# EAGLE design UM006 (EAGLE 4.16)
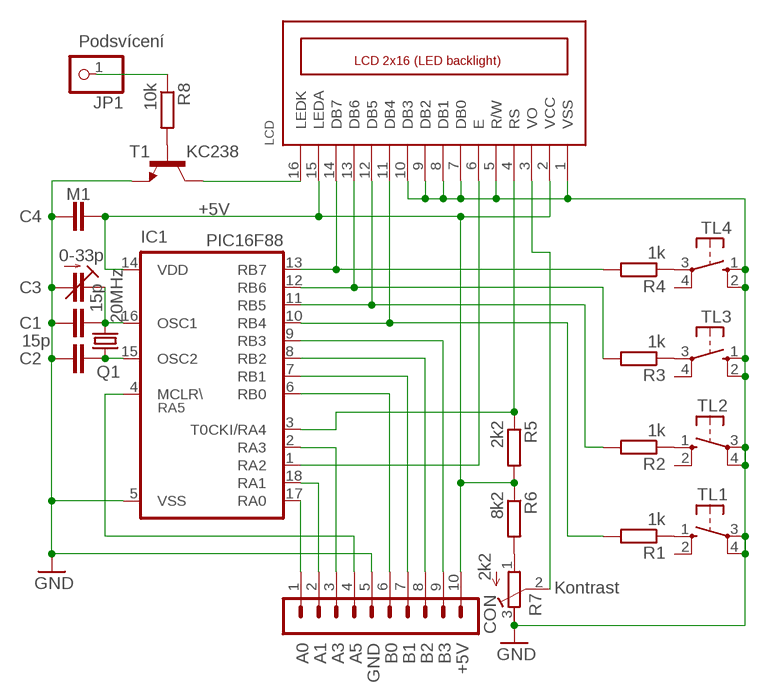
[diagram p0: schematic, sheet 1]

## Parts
C1  15p  C-EU025-024X044  [C025-024X044]
C2  15p  C-EU025-024X044  [C025-024X044]
C3  0-33p  C-TRIMM3008  [CTRIM3008]
C4  M1  C-EU025-024X044  [C025-024X044]
CON  MA10-1  [MA10-1]
IC1  PIC16F88  PIC16F84AP  [DIL18]
JP1  Podsvícení  PINHD-1X1  [1X01]
LCD  EL1602A  LCD_2X16_SIL  [HY-1602F]
Q1  20MHz  CRYSTALHC49U-H  [HC49U-H]
R1  1k  R-EU_0207/10  [0207/10]
R2  1k  R-EU_0207/10  [0207/10]
R3  1k  R-EU_0207/10  [0207/10]
R4  1k  R-EU_0207/10  [0207/10]
R5  2k2  R-EU_0204/5  [0204/5]
R6  8k2  R-EU_0204/2V  [0204V]
R7  2k2  R-TRIMM3339P  [RTRIM3339P]
R8  10k  R-EU_0207/10  [0207/10]
T1  KC238  BC548  [TO92-EBC]
TL1  10-XX  [B3F-10XX]
TL2  10-XX  [B3F-10XX]
TL3  10-XX  [B3F-10XX]
TL4  10-XX  [B3F-10XX]

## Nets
+5V: C4.1 CON.10 IC1.14(VDD) LCD.2(VCC) LCD.15(LEDA) R5.2 R6.1
A0: CON.1 IC1.17(RA0)
A1: CON.2 IC1.18(RA1)
A2_E: IC1.1(RA2) LCD.6(E)
A3: CON.3 IC1.2(RA3)
A4_RS: IC1.3(T0CKI/RA4) LCD.4(RS) R5.1
A5: CON.4 IC1.4(MCLR\)
B0: CON.6 IC1.6(RB0)
B1: CON.7 IC1.7(RB1)
B2: CON.8 IC1.8(RB2)
B3: CON.9 IC1.9(RB3)
B4_DB4: IC1.10(RB4) LCD.11(DB4) R1.2
B5_DB5: IC1.11(RB5) LCD.12(DB5) R2.2
B6_DB6: IC1.12(RB6) LCD.13(DB6) R3.2
B7_DB7: IC1.13(RB7) LCD.14(DB7) R4.2
GND: C1.1 C2.1 C3.-(A) C4.2 CON.5 IC1.5(VSS) LCD.1(VSS) LCD.5(R/W) LCD.7(DB0) LCD.8(DB1) LCD.9(DB2) LCD.10(DB3) R7.3(A) T1.E TL1.3(P) TL1.4(P1) TL2.3(P) TL2.4(P1) TL3.1(S) TL3.2(S1) TL4.1(S) TL4.2(S1)
LEDK: LCD.16(LEDK) T1.C
N$1: R6.2 R7.1(E)
N$11: R8.2 T1.B
N$26: JP1.1 R8.1
N$152: R4.1 TL4.3(P)
N$153: R3.1 TL3.3(P)
OSC1: C1.2 C3.+(E) IC1.16(OSC1) Q1.2
OSC2: C2.2 IC1.15(OSC2) Q1.1
TL1: R1.1 TL1.1(S)
TL2: R2.1 TL2.1(S)
VO: LCD.3(VO) R7.2(S)
Unconnected: TL1.2(S1) TL2.2(S1) TL3.4(P1) TL4.4(P1)

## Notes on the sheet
- +5V
- RA5
- Kontrast
- A0 | A1 | A3 | A5 | GND | B0 | B1 | B2 | B3 | +5V

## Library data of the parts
C1 C2 C4 = rcl:C-EU: CAPACITOR, European symbol
C3 = rcl:C-TRIMM: Trimm capacitor
CON = con-lstb:MA10-1: PIN HEADER
IC1 = microchip:PIC16F8*: MICROCONTROLLER 8-Bit PIC16F8X Family - CMOS Flash/EEPROM Pin Compatible : PIC16F83, PIC16CR83, PIC16F84A, PIC16CR84 see also PIC16C*
JP1 = pinhead:PINHD-1X1: PIN HEADER
LCD = lcd_2x16_led_backlight:LCD_2X16_SIL
Q1 = crystal:CRYSTAL: CRYSTAL
R1-R6 R8 = rcl:R-EU_: RESISTOR, European symbol
R7 = rcl:R-TRIMM: Trimm resistor
T1 = transistor-npn:BC548*: NPN Transistor
TL1-TL4 = switch-omron:10-XX: OMRON SWITCH

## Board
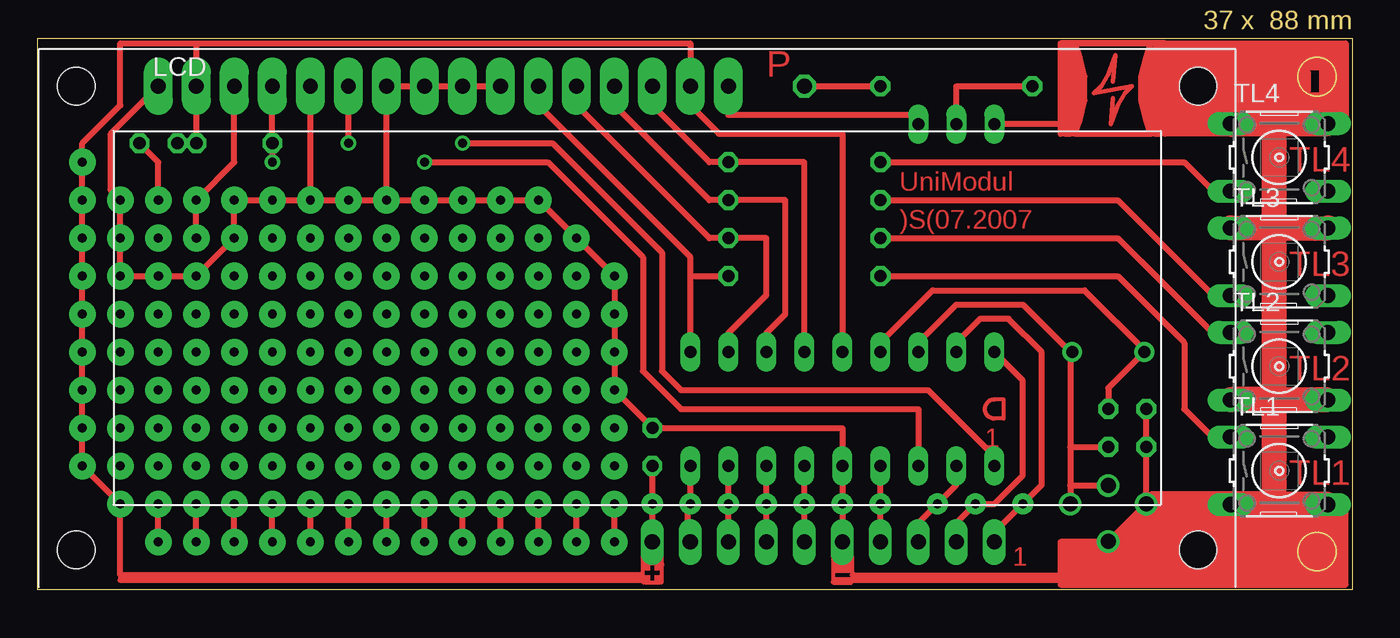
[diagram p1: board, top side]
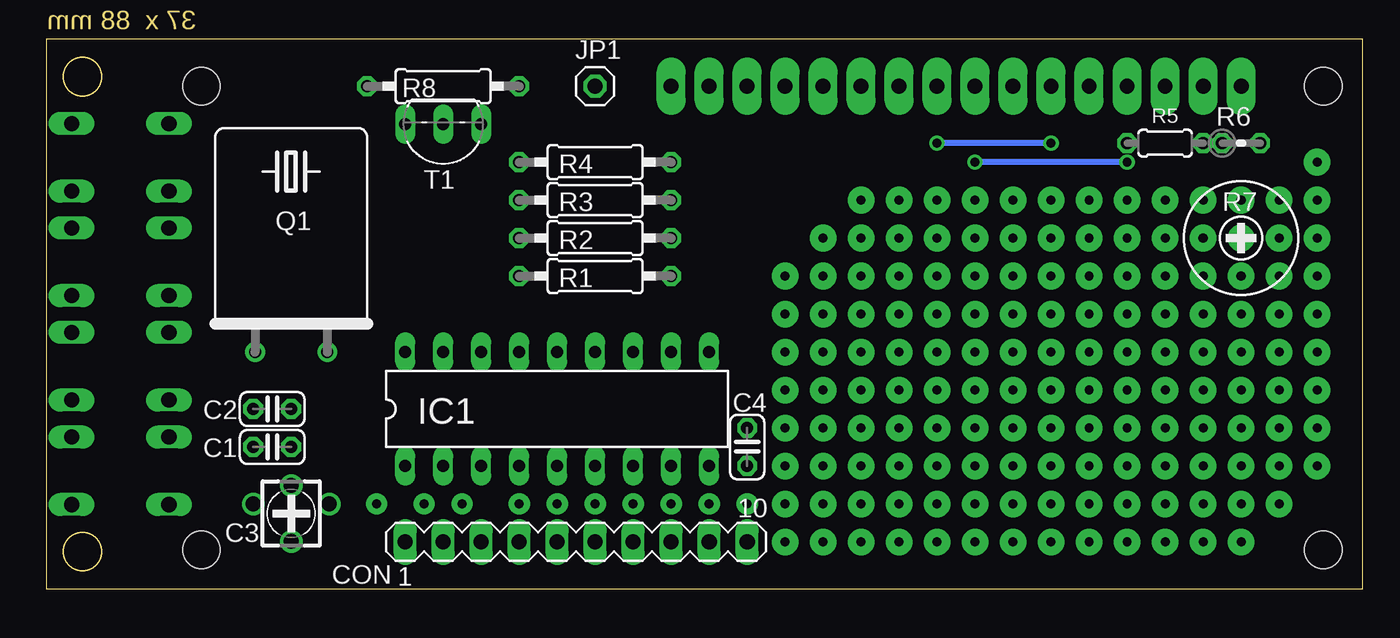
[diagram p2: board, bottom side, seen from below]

Size 87.94 x 36.82 mm. Coordinates in mm from the lower left corner, seen from the top.
Outline: 0,0 87.94,0 87.94,36.82 0,36.82 0,0
Outline: circle at 85.56,34.29 radius 1.27
Outline: circle at 85.56,2.54 radius 1.27
Copper layers (1*16): Top 0.035mm / dielectric 1.5mm / Bottom 0.035mm
Design rules "default": minimum track width 10mil, minimum drill 24mil, track to track 8mil, track to pad 8mil, pad to pad 8mil, via to via 8mil, smd to smd 8mil, copper to edge 40mil, drill to drill 8mil, minimum pad ring 10mil, minimum via ring 8mil, stop-mask expansion 4mil, vias tented up to drill 0mil, thermal gap 10mil

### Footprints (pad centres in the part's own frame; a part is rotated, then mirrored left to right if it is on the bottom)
C025-024X044 = drill 0.813 octagon: 1 -1.27,0; 2 1.27,0
CTRIM3008 = drill 1 round: + -1.875,0; - 1.875,0
MA10-1 = drill 1.016 long: 1 -11.43,0; 2 -8.89,0; 3 -6.35,0; 4 -3.81,0; 5 -1.27,0; 6 1.27,0; 7 3.81,0; 8 6.35,0; 9 8.89,0; 10 11.43,0
DIL18 = drill 0.813 long: 1 -10.16,-3.81; 2 -7.62,-3.81; 3 -5.08,-3.81; 4 -2.54,-3.81; 5 0,-3.81; 6 2.54,-3.81; 7 5.08,-3.81; 8 7.62,-3.81; 9 10.16,-3.81; 10 10.16,3.81; 11 7.62,3.81; 12 5.08,3.81; 13 2.54,3.81; 14 0,3.81; 15 -2.54,3.81; 16 -5.08,3.81; 17 -7.62,3.81; 18 -10.16,3.81
1X01 = drill 1.016 octagon: 1 0,0
HY-1602F = drill 1 pad 1.93 long: 1 2.54,0; 2 5.08,0; 3 7.62,0; 4 10.16,0; 5 12.7,0; 6 15.24,0; 7 17.78,0; 8 20.32,0; 9 22.86,0; 10 25.4,0; 11 27.94,0; 12 30.48,0; 13 33.02,0; 14 35.56,0; 15 38.1,0; 16 40.64,0 | hole 2.5: -2.96,0; 72.04,0; -2.96,-31; 72.04,-31
HC49U-H = drill 0.813 round: 1 -2.413,-5.08; 2 2.413,-5.08
0207/10 = drill 0.813 octagon: 1 -5.08,0; 2 5.08,0
0204/5 = drill 0.813 octagon: 1 -2.54,0; 2 2.54,0
0204V = drill 0.813 octagon: 1 -1.27,0; 2 1.27,0
RTRIM3339P = drill 0.61 round: 1 -2.54,0; 2 0,-2.54; 3 2.54,0
TO92-EBC = drill 0.813 long: B 0,-1.27; C -2.54,-1.27; E 2.54,-1.27
B3F-10XX = drill 1.016 long: 1 -3.251,2.261; 2 3.251,2.261; 3 -3.251,-2.261; 4 3.251,-2.261

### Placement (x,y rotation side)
C1  72.86,9.52 0 bottom
C2  72.86,12.06 0 bottom
C3  71.59,5.08 270 bottom
C4  41.11,9.52 90 bottom
CON  52.54,3.17 0 bottom
IC1  53.81,12.06 0 bottom
JP1  51.27,33.65 0 bottom
LCD  5.55,33.65 0 top
Q1  71.59,20.95 0 bottom
R1  51.27,20.95 0 bottom
R2  51.27,23.49 0 bottom
R3  51.27,26.03 0 bottom
R4  51.27,28.57 0 bottom
R5  13.17,29.84 0 bottom
R6  8.09,29.84 0 bottom
R7  8.09,23.49 270 bottom
R8  61.43,33.65 180 bottom
T1  61.43,29.84 180 bottom
TL1  83.02,7.93 0 top
TL2  83.02,14.92 0 top
TL3  83.02,21.9 0 top
TL4  83.02,28.89 0 top

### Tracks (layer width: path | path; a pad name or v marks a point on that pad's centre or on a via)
+5V  (via drill 0.6 pad 1.42)
  Top 0.254: 40.48,0.95 40.32,0.95 | 40.48,0.95 40.48,2.22 41.11,2.85 41.75,2.22 41.75,1.58 | 41.75,1.58 41.75,0.47 40.48,0.47 40.48,0.63 40.48,0.95 | 41.75,1.58 41.75,1.74 40.48,1.74 40.48,0.95
  Top 0.406: 10.63,36.51 LCD.2 R5.2 R6.1 | 10.63,36.51 43.65,36.51 LCD.15 43.65,32.38 45.55,30.47 53.81,30.47 IC1.14 | 10.63,36.51 5.55,36.51 5.55,32.38 3.01,29.84 3.01,8.25 5.55,5.71 5.55,0.95 40.32,0.95 | 5.55,0.63 40.48,0.63 | C4.1 v41.11,5.71 CON.10 | CON.10 | CON.10 41.11,2.85
A0
  Top 0.406: IC1.17 61.43,16.5 63.02,18.09 64.92,18.09 67.14,15.87 67.14,6.98 63.97,3.8 CON.1
A1
  Top 0.406: IC1.18 65.88,13.96 65.88,7.62 63.97,5.71 62.7,5.71 61.43,4.44 CON.2
A2_E  (via drill 0.6)
  Top 0.406: v20.79,29.84 LCD.6 | IC1.1 63.97,8.88 59.53,13.33 43.02,13.33 41.75,14.6 41.75,22.54 34.44,29.84 v28.41,29.84
  Bottom 0.406: v20.79,29.84 v28.41,29.84
A3
  Top 0.406: IC1.2 61.43,6.98 58.89,4.44 CON.3
A4_RS  (via drill 0.6)
  Top 0.406: IC1.3 58.89,12.06 43.02,12.06 40.48,14.6 40.48,22.22 34.12,28.57 v25.87,28.57 | LCD.4 R5.1 v15.71,28.57
  Bottom 0.406: v15.71,28.57 v25.87,28.57
A5  (via drill 0.6 pad 1.42)
  Top 0.406: IC1.4 v56.35,5.71 CON.4
B0  (via drill 0.6 pad 1.42)
  Top 0.406: IC1.6 v51.27,5.71 CON.6
B1  (via drill 0.6 pad 1.42)
  Top 0.406: IC1.7 v48.73,5.71 CON.7
B2  (via drill 0.6 pad 1.42)
  Top 0.406: IC1.8 v46.19,5.71 CON.8
B3  (via drill 0.6 pad 1.42)
  Top 0.406: IC1.9 v43.65,5.71 43.49,5.71 43.49,3.17 CON.9
B4_DB4
  Top 0.406: IC1.10 43.65,20.95 | LCD.11 33.49,32.38 43.65,22.22 43.65,20.95 | 43.65,20.95 R1.2
B5_DB5
  Top 0.406: LCD.12 36.03,32.38 44.92,23.49 R2.2 48.73,23.49 48.73,19.68 46.19,17.14 IC1.11
B6_DB6
  Top 0.406: LCD.13 38.57,32.38 44.92,26.03 R3.2 50,26.03 50,18.41 48.73,17.14 IC1.12
B7_DB7
  Top 0.406: LCD.14 41.11,32.38 44.92,28.57 R4.2 51.27,28.57 IC1.13
GND  (via drill 0.6 pad 1.42, 0.6 pad 1.78, 1)
  Top 0.254: 54.45,0.95 54.6,0.95 | 54.45,0.95 54.45,2.22 53.81,2.85 53.73,2.77 53.18,2.22 53.18,0.47 | 54.45,0.47 54.45,0.63 54.45,0.95
  Top 0.406: 83.02,5.71 83.02,12.7 83.02,24.12 83.02,31.11 TL4.1 79.77,30.47 | 54.6,0.95 71.59,0.95 71.59,3.17 | 83.02,5.71 83.34,5.71 83.34,30.79 | 80.16,5.71 80.48,5.71 | 80.48,5.71 80.8,5.71 | 80.8,5.71 81.75,5.71 | 82.07,5.71 82.39,5.71 | 82.7,5.71 83.02,5.71 | 79.84,5.71 79.81,5.71 | 79.84,5.71 79.81,5.67 TL1.3 79.73,5.71 78.89,5.71 | TL1.4 86.23,5.67 86.2,5.71 86.23,5.71 | TL2.4 86.23,12.66 86.2,12.7 86.23,12.7 | 79.81,12.7 TL2.3 | v74.13,5.71 74.45,5.71 | 74.45,5.71 74.77,5.71 | 75.4,5.71 75.08,5.71 | 76.67,5.71 75.72,5.71 | 76.99,5.71 77.31,5.71 | 77.62,5.71 77.94,5.71 | 78.26,5.71 78.58,5.71 | 72.54,4.12 71.62,3.2 | 72.54,4.12 73.5,5.08 | 73.81,5.39 v74.13,5.71 | LCD.10 LCD.9 LCD.8 LCD.7 23.33,26.03 | LCD.1 4.92,30.47 4.92,26.66 v5.55,26.03 v5.55,20.95 R7.3 10.63,20.95 13.17,23.49 v13.17,26.03 v15.71,26.03 v18.25,26.03 | 23.33,26.03 33.49,26.03 38.57,20.95 38.57,13.33 C4.2 53.81,10.79 IC1.5 v53.81,5.71 CON.5 | v18.25,26.03 23.33,26.03 | v18.25,26.03 LCD.5 | 79.77,30.47 79.84,31.11 | 75.4,30.47 69.37,30.47 | 69.37,30.47 68.42,30.47 68.42,31.11 | 69.37,30.47 74.45,30.47 74.13,31.43 73.81,32.7 73.81,34.29 74.13,35.56 74.45,36.51 69.37,36.51 69.69,35.56 70,34.29 70,32.7 69.69,31.43 69.37,30.47 | 68.42,31.11 68.42,36.51 75.4,36.51 | 75.4,30.79 75.4,31.11 | 75.4,31.11 75.4,36.51 | 75.4,36.51 87.47,36.51 87.47,31.43 75.72,31.43 75.72,36.19 87.15,36.19 87.15,31.75 76.03,31.75 76.03,35.87 86.83,35.87 86.83,32.06 76.35,32.06 76.35,35.56 86.51,35.56 86.51,32.38 76.67,32.38 76.67,35.24 86.2,35.24 86.2,32.7 76.99,32.7 76.99,34.92 85.88,34.92 85.88,33.02 77.31,33.02 77.31,34.6 84.92,34.6 84.92,34.29
  Top 0.406: 84.92,33.65 84.92,33.33 77.62,33.33 77.62,34.29 84.92,34.29 | 84.92,34.29 84.92,33.97 | 84.92,33.97 84.92,33.65 | 84.92,33.65 77.94,33.65 77.94,33.97 84.92,33.97 | 82.7,5.71 82.7,31.11 | 82.39,5.71 82.7,5.71 | 82.39,5.71 82.39,30.79 82.07,30.79 | 82.07,6.35 82.07,30.47 | 82.07,6.03 82.07,6.35 | 82.07,5.71 82.07,6.03 | 87.47,5.71 87.47,0.31 68.42,0.31 68.42,0.63 | 68.42,0.63 68.42,3.17 71.59,3.17 | 71.59,3.17 71.59,0.63 | 71.59,0.63 68.73,0.63 68.73,2.85 71.27,2.85 71.27,1.26 | 81.12,0.63 81.43,0.63 | 81.75,0.63 87.15,0.63 | 87.15,0.95 87.15,5.71 86.83,5.71 86.83,0.95 86.51,0.95 86.51,5.39 86.2,5.39 86.2,0.95 85.88,0.95 85.88,5.39 85.56,5.39 85.56,0.95 85.24,0.95 85.24,5.39 84.92,5.39 84.92,0.95 84.61,0.95 | 84.61,5.71 84.29,5.71 84.29,0.95 83.97,0.95 83.97,5.39 83.66,5.39 83.66,0.95 83.34,0.95 83.34,5.39 83.02,5.39 83.02,0.95 | 82.7,0.95 82.7,5.39 82.39,5.39 82.39,0.95 82.07,0.95 82.07,5.71 | 81.75,5.71 82.07,5.71 | 81.75,0.63 81.75,5.71 | 81.43,0.63 81.75,0.63 | 81.43,0.63 81.43,5.39 81.12,5.39 81.12,0.63 | 71.59,0.63 71.91,0.63 | 72.23,0.63 76.35,0.63 | 76.67,0.63 79.53,0.63 | 79.84,0.63 80.16,0.63 | 80.48,0.63 81.12,0.63 | 80.8,5.71 80.8,0.95 | 80.48,0.63 80.48,5.71 | 80.16,0.63 80.48,0.63 | 80.16,0.63 80.16,5.71 | 79.84,5.71 80.16,5.71 | 79.84,0.63 79.84,5.71 | 79.53,0.63 79.84,0.63 | 79.53,0.63 79.53,5.39 79.21,5.39 79.21,0.95 78.89,0.95 78.89,5.71 | 78.89,5.71 78.58,5.71 | 78.58,5.71 78.58,0.95 78.26,0.95 78.26,5.71 | 77.94,5.71 78.26,5.71 | 77.94,5.71 77.94,0.95 77.62,0.95 77.62,5.71 | 77.31,5.71 77.62,5.71 | 77.31,5.71 77.31,0.95 76.99,0.95 76.99,5.71 | 76.67,5.71 76.99,5.71 | 76.67,0.63 76.67,5.71
  Top 0.406: 76.35,0.63 76.67,0.63 | 76.35,0.63 76.35,5.39 76.03,5.39 76.03,0.95 75.72,0.95 75.72,5.71 | 75.72,5.71 75.4,5.71 | 75.4,5.71 75.4,0.95 75.08,0.95 75.08,5.71 | 75.08,5.71 74.77,5.71 | 74.77,5.71 74.77,0.95 74.45,0.95 74.45,5.71 | 74.45,5.71 74.13,5.39 74.13,0.95 73.81,0.95 73.81,5.39 | 73.5,5.08 73.81,5.39 | 73.5,5.08 73.5,0.95 73.18,0.95 73.18,4.44 72.86,4.12 72.86,0.95 72.54,0.95 72.54,4.12 | 72.54,4.12 72.23,3.49 72.23,0.63 | 71.91,0.63 72.23,0.63 | 71.91,0.63 71.91,3.17 | 75.4,31.11 79.53,31.11 79.53,30.79 75.4,30.79 | 75.4,30.47 75.4,30.79 | 79.77,30.47 75.4,30.47 | 82.07,30.47 79.84,30.47 | 82.07,30.79 82.07,30.47 | 82.07,30.79 80.16,30.79 | 82.07,6.03 74.45,6.03 74.45,6.35 82.07,6.35 | 54.45,0.63 68.42,0.63 | 68.42,31.11 T1.E | C2.1 C1.1 v74.13,5.71 | 71.59,3.17 C3.- | CON.5 | 53.81,2.77 53.81,2.69 | 53.81,2.77 53.73,2.77 | CON.5 53.81,2.77
  Top 1.676: 83.34,5.71 84.29,5.71 | 86.2,5.71 84.61,5.71 84.61,0.95 | 86.2,12.7 83.02,12.7 79.81,12.7 | 83.02,31.11 TL4.2 | TL3.2 83.02,24.12 TL3.1
LEDK
  Top 0.406: LCD.16 46.19,31.75 58.89,31.75 T1.C
N$1
  Top 0.406: R7.1 8.09,28.57 R6.2
N$2  (via drill 0.6 pad 1.78)
  other vias: 8.09,23.49
N$3  (via drill 0.6 pad 1.78)
  other vias: 8.09,20.95
N$4  (via drill 0.6 pad 1.78)
  other vias: 13.17,23.49
N$5  (via drill 0.6 pad 1.78)
  other vias: 10.63,26.03
N$6  (via drill 0.6 pad 1.78)
  other vias: 10.63,20.95
N$7  (via drill 0.6 pad 1.78)
  other vias: 5.55,23.49
N$8  (via drill 0.6 pad 1.78)
  other vias: 8.09,26.03
N$9  (via drill 0.6 pad 1.78)
  other vias: 23.33,26.03
N$11
  Top 0.406: T1.B 61.43,33.65 R8.2
N$12  (via drill 0.6 pad 1.78)
  other vias: 20.79,26.03
N$13  (via drill 0.6 pad 1.78)
  other vias: 10.63,23.49
N$14  (via drill 0.6 pad 1.78)
  other vias: 38.57,13.33
N$15  (via drill 0.6 pad 1.78)
  other vias: 38.57,15.87
N$16  (via drill 0.6 pad 1.78)
  other vias: 38.57,18.41
N$17  (via drill 0.6 pad 1.78)
  other vias: 38.57,20.95
N$18  (via drill 0.6 pad 1.78)
  other vias: 36.03,23.49
N$19  (via drill 0.6 pad 1.78)
  other vias: 33.49,26.03
N$20  (via drill 0.6 pad 1.78)
  other vias: 30.95,26.03
N$21  (via drill 0.6 pad 1.78)
  other vias: 28.41,26.03
N$22  (via drill 0.6 pad 1.78)
  other vias: 25.87,26.03
N$23  (via drill 0.6 pad 1.78)
  other vias: 5.55,5.71
N$24  (via drill 0.6 pad 1.78)
  other vias: 38.57,10.79
N$25  (via drill 0.6 pad 1.78)
  other vias: 3.01,8.25
N$26
  Top 0.406: 51.11,33.65 JP1.1 R8.1
N$27  (via drill 0.6 pad 1.78)
  other vias: 38.57,8.25
N$28  (via drill 0.6 pad 1.78)
  Top 0.406: v38.57,3.17 v38.57,5.71
N$30  (via drill 0.6 pad 1.78)
  other vias: 36.03,20.95
N$31  (via drill 0.6 pad 1.78)
  other vias: 36.03,18.41
N$32  (via drill 0.6 pad 1.78)
  other vias: 36.03,15.87
N$33  (via drill 0.6 pad 1.78)
  other vias: 36.03,13.33
N$34  (via drill 0.6 pad 1.78)
  other vias: 36.03,10.79
N$35  (via drill 0.6 pad 1.78)
  other vias: 36.03,8.25
N$36  (via drill 0.6 pad 1.78)
  Top 0.406: v36.03,3.17 v36.03,5.71
N$38  (via drill 0.6 pad 1.78)
  other vias: 33.49,23.49
N$39  (via drill 0.6 pad 1.78)
  other vias: 33.49,20.95
N$40  (via drill 0.6 pad 1.78)
  other vias: 33.49,18.41
N$41  (via drill 0.6 pad 1.78)
  other vias: 33.49,15.87
N$42  (via drill 0.6 pad 1.78)
  other vias: 33.49,13.33
N$43  (via drill 0.6 pad 1.78)
  other vias: 33.49,10.79
N$44  (via drill 0.6 pad 1.78)
  other vias: 33.49,8.25
N$45  (via drill 0.6 pad 1.78)
  Top 0.406: v33.49,3.17 v33.49,5.71
N$48  (via drill 0.6 pad 1.78)
  Top 0.406: v30.95,3.17 v30.95,5.71
N$49  (via drill 0.6 pad 1.78)
  other vias: 30.95,8.25
N$50  (via drill 0.6 pad 1.78)
  other vias: 30.95,10.79
N$51  (via drill 0.6 pad 1.78)
  other vias: 30.95,13.33
N$52  (via drill 0.6 pad 1.78)
  other vias: 30.95,15.87
N$53  (via drill 0.6 pad 1.78)
  other vias: 30.95,18.41
N$54  (via drill 0.6 pad 1.78)
  other vias: 30.95,20.95
N$55  (via drill 0.6 pad 1.78)
  other vias: 30.95,23.49
N$56  (via drill 0.6 pad 1.78)
  other vias: 28.41,23.49
N$57  (via drill 0.6 pad 1.78)
  other vias: 28.41,20.95
N$58  (via drill 0.6 pad 1.78)
  other vias: 28.41,18.41
N$59  (via drill 0.6 pad 1.78)
  other vias: 28.41,15.87
N$60  (via drill 0.6 pad 1.78)
  other vias: 28.41,13.33
N$61  (via drill 0.6 pad 1.78)
  other vias: 28.41,10.79
N$62  (via drill 0.6 pad 1.78)
  other vias: 28.41,8.25
N$63  (via drill 0.6 pad 1.78)
  Top 0.406: v28.41,3.17 v28.41,5.71
N$66  (via drill 0.6 pad 1.78)
  Top 0.406: v25.87,3.17 v25.87,5.71
N$67  (via drill 0.6 pad 1.78)
  other vias: 25.87,8.25
N$68  (via drill 0.6 pad 1.78)
  other vias: 25.87,10.79
N$69  (via drill 0.6 pad 1.78)
  other vias: 25.87,13.33
N$70  (via drill 0.6 pad 1.78)
  other vias: 25.87,15.87
N$71  (via drill 0.6 pad 1.78)
  other vias: 25.87,18.41
N$72  (via drill 0.6 pad 1.78)
  other vias: 25.87,20.95
N$73  (via drill 0.6 pad 1.78)
  other vias: 25.87,23.49
N$74  (via drill 0.6 pad 1.78)
  other vias: 23.33,23.49
N$75  (via drill 0.6 pad 1.78)
  other vias: 23.33,20.95
N$76  (via drill 0.6 pad 1.78)
  other vias: 23.33,18.41
N$77  (via drill 0.6 pad 1.78)
  other vias: 23.33,15.87
N$78  (via drill 0.6 pad 1.78)
  other vias: 23.33,13.33
N$79  (via drill 0.6 pad 1.78)
  other vias: 23.33,10.79
N$80  (via drill 0.6 pad 1.78)
  other vias: 23.33,8.25
N$81  (via drill 0.6 pad 1.78)
  Top 0.406: v23.33,3.17 v23.33,5.71
N$84  (via drill 0.6 pad 1.78)
  Top 0.406: v20.79,3.17 v20.79,5.71
N$85  (via drill 0.6 pad 1.78)
  other vias: 20.79,8.25
N$86  (via drill 0.6 pad 1.78)
  other vias: 20.79,10.79
N$87  (via drill 0.6 pad 1.78)
  other vias: 20.79,13.33
N$88  (via drill 0.6 pad 1.78)
  other vias: 20.79,15.87
N$89  (via drill 0.6 pad 1.78)
  other vias: 20.79,18.41
N$90  (via drill 0.6 pad 1.78)
  other vias: 20.79,20.95
N$91  (via drill 0.6 pad 1.78)
  other vias: 20.79,23.49
N$92  (via drill 0.6 pad 1.78)
  other vias: 18.25,23.49
N$93  (via drill 0.6 pad 1.78)
  other vias: 18.25,20.95
N$94  (via drill 0.6 pad 1.78)
  other vias: 18.25,18.41
N$95  (via drill 0.6 pad 1.78)
  other vias: 18.25,15.87
N$96  (via drill 0.6 pad 1.78)
  other vias: 18.25,13.33
N$97  (via drill 0.6 pad 1.78)
  other vias: 18.25,10.79
N$98  (via drill 0.6 pad 1.78)
  other vias: 18.25,8.25
N$99  (via drill 0.6 pad 1.78)
  Top 0.406: v18.25,3.17 v18.25,5.71
N$102  (via drill 0.6 pad 1.78)
  Top 0.406: v15.71,3.17 v15.71,5.71
N$103  (via drill 0.6 pad 1.78)
  other vias: 15.71,8.25
N$104  (via drill 0.6 pad 1.78)
  other vias: 15.71,10.79
N$105  (via drill 0.6 pad 1.78)
  other vias: 15.71,13.33
N$106  (via drill 0.6 pad 1.78)
  other vias: 15.71,15.87
N$107  (via drill 0.6 pad 1.78)
  other vias: 15.71,18.41
N$108  (via drill 0.6 pad 1.78)
  other vias: 15.71,20.95
N$109  (via drill 0.6 pad 1.78)
  other vias: 15.71,23.49
N$110  (via drill 0.6 pad 1.78)
  other vias: 13.17,20.95
N$111  (via drill 0.6 pad 1.78)
  other vias: 13.17,18.41
N$112  (via drill 0.6 pad 1.78)
  other vias: 13.17,15.87
N$113  (via drill 0.6 pad 1.78)
  other vias: 13.17,13.33
N$114  (via drill 0.6 pad 1.78)
  other vias: 13.17,10.79
N$115  (via drill 0.6 pad 1.78)
  other vias: 13.17,8.25
N$116  (via drill 0.6 pad 1.78)
  Top 0.406: v13.17,3.17 v13.17,5.71
N$119  (via drill 0.6 pad 1.78)
  Top 0.406: v10.63,3.17 v10.63,5.71
N$120  (via drill 0.6 pad 1.78)
  other vias: 10.63,8.25
N$121  (via drill 0.6 pad 1.78)
  other vias: 10.63,10.79
N$122  (via drill 0.6 pad 1.78)
  other vias: 10.63,13.33
N$123  (via drill 0.6 pad 1.78)
  other vias: 10.63,15.87
N$124  (via drill 0.6 pad 1.78)
  other vias: 10.63,18.41
N$125  (via drill 0.6 pad 1.78)
  other vias: 8.09,18.41
N$126  (via drill 0.6 pad 1.78)
  other vias: 8.09,15.87
N$127  (via drill 0.6 pad 1.78)
  other vias: 8.09,13.33
N$128  (via drill 0.6 pad 1.78)
  other vias: 8.09,10.79
N$129  (via drill 0.6 pad 1.78)
  other vias: 8.09,8.25
N$130  (via drill 0.6 pad 1.78)
  Top 0.406: v8.09,3.17 v8.09,5.71
N$132  (via drill 0.6 pad 1.78)
  other vias: 5.55,8.25
N$133  (via drill 0.6 pad 1.78)
  other vias: 5.55,10.79
N$134  (via drill 0.6 pad 1.78)
  other vias: 5.55,13.33
N$135  (via drill 0.6 pad 1.78)
  other vias: 5.55,15.87
N$136  (via drill 0.6 pad 1.78)
  other vias: 3.01,10.79
N$137  (via drill 0.6 pad 1.78)
  other vias: 3.01,13.33
N$138  (via drill 0.6 pad 1.78)
  other vias: 3.01,15.87
N$139  (via drill 0.6 pad 1.78)
  other vias: 3.01,18.41
N$140  (via drill 0.6 pad 1.78)
  other vias: 3.01,20.95
N$141  (via drill 0.6 pad 1.78)
  other vias: 3.01,23.49
N$142  (via drill 0.6 pad 1.78)
  other vias: 3.01,26.03
N$143  (via drill 0.6 pad 1.78)
  other vias: 3.01,28.57
N$144  (via drill 0.6 pad 1.42)
  other vias: 65.88,5.71
N$145  (via drill 0.6 pad 1.42)
  other vias: 62.7,5.71
N$146
  Top 0.406: 68.73,36.19 69.05,36.19 69.69,34.29 69.69,32.7 69.05,30.47 68.73,30.47 68.73,35.87 69.37,34.29 69.37,32.7 69.05,30.79 69.05,34.6
N$147
  Top 0.406: 74.77,36.19 74.13,34.29 74.13,32.7 74.77,30.47 | 74.77,30.47 75.08,30.47 75.08,36.19 74.45,34.29 74.45,32.7 74.77,30.47 | 74.77,30.47 74.77,34.92
N$148
  Top 0.406: 70.95,1.26 69.05,1.26 69.05,2.54 70.95,2.54 70.95,1.58 69.37,1.58 69.37,2.22 70.64,2.22 70.64,1.9 69.69,1.9
N$149
  Top 0.254: 64.61,12.7 63.97,12.7 arc90 63.34,12.06 arc90 63.97,11.43 64.61,11.43 64.61,12.7
N$150  (via drill 0.6 pad 1.78)
  other vias: 5.55,18.41
N$151  (via drill 0.6 pad 1.42)
  other vias: 60.16,5.71
N$152
  Top 0.406: TL4.3 79.81,26.63 78.58,26.66 76.67,28.57 R4.1
N$153
  Top 0.406: TL3.3 79.81,19.64 78.58,19.68 72.23,26.03 R3.1
OSC1  (via drill 1)
  Top 0.406: IC1.16 58.89,16.5 61.43,19.04 65.88,19.04 69.05,15.87 | 69.05,15.87 Q1.2 | 69.05,6.95 v69.05,5.71 | 69.05,15.87 69.05,9.52 | 69.05,9.52 C1.2 | 69.05,6.95 C3.+ | 69.05,9.52 69.05,6.95
OSC2
  Top 0.406: IC1.15 56.35,16.5 59.84,20 70,20 74.13,15.87 Q1.1 71.59,13.46 C2.2
S$3
  Top 0.305: 71.91,32.86 71.75,31.11 72.23,32.38 72.7,33.17 73.18,33.65 70.64,33.17 71.11,33.65 71.59,34.44 72.07,35.71 71.91,33.97
TL1
  Top 0.406: TL1.1 79.81,10.19 79.84,10.15 78.58,10.15 76.67,12.06 76.67,16.5 72.23,20.95 R1.1
TL2
  Top 0.406: 79.81,17.14 79.84,17.14 | 79.81,17.14 TL2.1 | 79.81,17.14 78.58,17.14 72.23,23.49 R2.1
VO
  Top 0.406: 10.71,26.11 10.63,26.03 | 10.71,26.11 13.17,28.57 LCD.3 | 10.71,26.11 10.63,26.19 R7.2
(copper drawn outside any net)
  shapes: Top area x6

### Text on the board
Top: P | TL4 | UniModul | )S(07.2007 | TL3 | TL2 | 1 | TL1 | 1
Dimension: 37 x 88 mm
